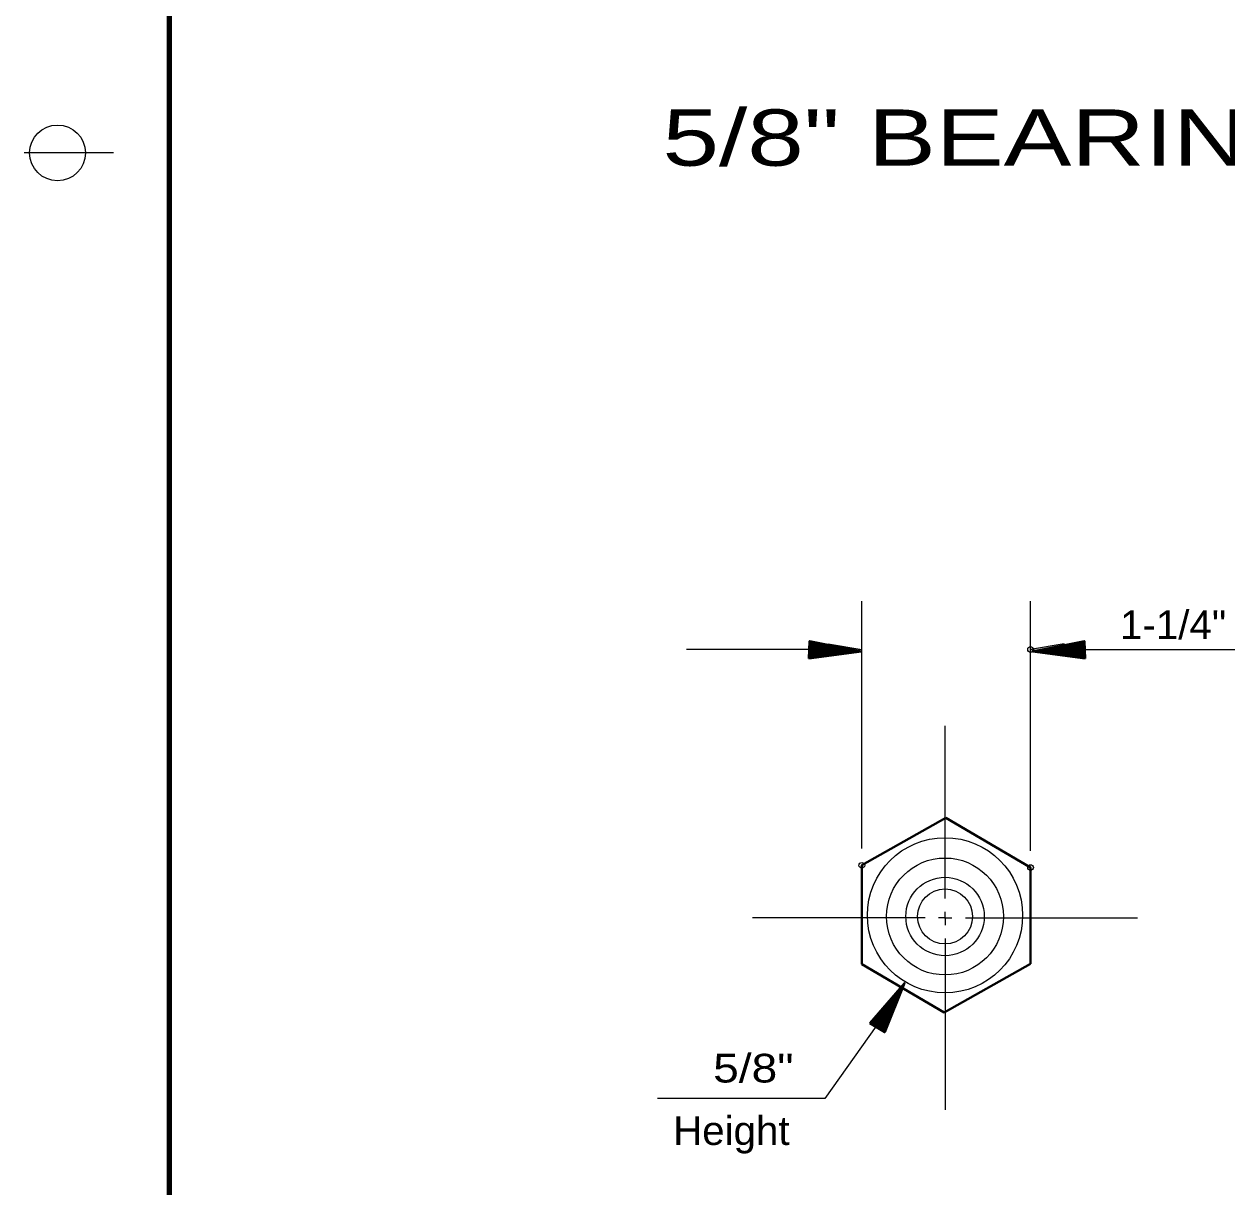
# Model space of a CAD drawing. Extents: x 895.6 to 930.4, y -2278.6 to -2254.7.
# Drawn here: x 896.79 to 902.18, y -2267.5 to -2262.29 of the extents above; entities that cross this region are included whole.
import ezdxf
from ezdxf.enums import TextEntityAlignment as Align

# ---------------------------------------------------------------- set-up
doc = ezdxf.new("R2010")
doc.units = 0
doc.header["$LTSCALE"] = 0.051
doc.header["$PDMODE"] = 32
doc.header["$PDSIZE"] = 0.0255
for name, color, linetype, lineweight in [('1', 7, 'Continuous', 70), ('3', 7, 'Continuous', 40), ('5', 7, 'Continuous', 25), ('6', 7, 'Continuous', 13)]:
    doc.layers.add(name, color=color, linetype=linetype, lineweight=lineweight)

msp = doc.modelspace()

# ---------------------------------------------------------------- hatches: boundary and pattern name
at = {"layer": '1'}
for points in [[(900.39442, -2265.11317), (900.39442, -2265.063), (900.545, -2265.08808), (900.545, -2265.08808)], [(901.45133, -2265.11317), (901.45133, -2265.063), (901.30075, -2265.08808), (901.30075, -2265.08808)]]:
    msp.add_hatch(color=256, dxfattribs=at).paths.add_polyline_path(points)
at = {"layer": '3'}
for points in [[(900.308, -2265.12892), (900.31067, -2265.05092), (900.54333, -2265.09783), (900.54333, -2265.09783)], [(900.30925, -2265.125), (900.31158, -2265.05483), (900.52092, -2265.097), (900.52092, -2265.097)], [(901.545, -2265.12892), (901.54233, -2265.05092), (901.30967, -2265.09783), (901.30967, -2265.09783)], [(901.54375, -2265.125), (901.54142, -2265.05483), (901.33208, -2265.097), (901.33208, -2265.097)], [(900.31025, -2265.1215), (900.31242, -2265.05842), (900.50083, -2265.09642), (900.50083, -2265.09642)], [(900.31125, -2265.11842), (900.31317, -2265.06167), (900.48275, -2265.09583), (900.48275, -2265.09583)], [(900.312, -2265.11575), (900.31383, -2265.06458), (900.4665, -2265.09533), (900.4665, -2265.09533)], [(900.313, -2265.11308), (900.3145, -2265.06708), (900.45183, -2265.09483), (900.45183, -2265.09483)], [(900.31358, -2265.11075), (900.31492, -2265.06933), (900.43867, -2265.09433), (900.43867, -2265.09433)], [(900.31433, -2265.10883), (900.31542, -2265.0715), (900.42667, -2265.094), (900.42667, -2265.094)], [(900.31467, -2265.107), (900.316, -2265.07333), (900.41608, -2265.0935), (900.41608, -2265.0935)], [(900.31533, -2265.10525), (900.31642, -2265.07492), (900.40642, -2265.09325), (900.40642, -2265.09325)], [(900.31583, -2265.10375), (900.31675, -2265.07658), (900.39775, -2265.09292), (900.39775, -2265.09292)], [(900.31617, -2265.10233), (900.31708, -2265.078), (900.39, -2265.09258), (900.39, -2265.09258)], [(900.31667, -2265.10125), (900.31733, -2265.07917), (900.38283, -2265.09242), (900.38283, -2265.09242)], [(900.31708, -2265.10008), (900.31758, -2265.08025), (900.37675, -2265.09225), (900.37675, -2265.09225)], [(900.31733, -2265.09917), (900.31792, -2265.08125), (900.371, -2265.09208), (900.371, -2265.09208)], [(900.31758, -2265.09825), (900.318, -2265.08208), (900.36592, -2265.09175), (900.36592, -2265.09175)], [(900.31783, -2265.09742), (900.31833, -2265.08283), (900.36133, -2265.09158), (900.36133, -2265.09158)], [(900.318, -2265.09667), (900.31842, -2265.08367), (900.35725, -2265.0915), (900.35725, -2265.0915)], [(900.31833, -2265.09625), (900.31858, -2265.08442), (900.35358, -2265.0915), (900.35358, -2265.0915)], [(900.3185, -2265.09567), (900.31883, -2265.08508), (900.35033, -2265.09142), (900.35033, -2265.09142)], [(900.31875, -2265.09533), (900.31908, -2265.08575), (900.34733, -2265.09158), (900.34733, -2265.09158)], [(900.31875, -2265.09475), (900.31908, -2265.08625), (900.34458, -2265.09142), (900.34458, -2265.09142)], [(900.31892, -2265.09425), (900.31925, -2265.08667), (900.34217, -2265.09117), (900.34217, -2265.09117)], [(900.31908, -2265.094), (900.31933, -2265.08717), (900.34, -2265.09125), (900.34, -2265.09125)], [(901.54275, -2265.1215), (901.54058, -2265.05842), (901.35217, -2265.09642), (901.35217, -2265.09642)], [(901.54175, -2265.11842), (901.53983, -2265.06167), (901.37025, -2265.09583), (901.37025, -2265.09583)], [(901.541, -2265.11575), (901.53917, -2265.06458), (901.3865, -2265.09533), (901.3865, -2265.09533)], [(901.54, -2265.11308), (901.5385, -2265.06708), (901.40117, -2265.09483), (901.40117, -2265.09483)], [(901.53942, -2265.11075), (901.53808, -2265.06933), (901.41433, -2265.09433), (901.41433, -2265.09433)], [(901.53867, -2265.10883), (901.53758, -2265.0715), (901.42633, -2265.094), (901.42633, -2265.094)], [(901.53833, -2265.107), (901.537, -2265.07333), (901.43692, -2265.0935), (901.43692, -2265.0935)], [(901.53767, -2265.10525), (901.53658, -2265.07492), (901.44658, -2265.09325), (901.44658, -2265.09325)], [(901.53717, -2265.10375), (901.53625, -2265.07658), (901.45525, -2265.09292), (901.45525, -2265.09292)], [(901.53683, -2265.10233), (901.53592, -2265.078), (901.463, -2265.09258), (901.463, -2265.09258)], [(901.53633, -2265.10125), (901.53567, -2265.07917), (901.47017, -2265.09242), (901.47017, -2265.09242)], [(901.53592, -2265.10008), (901.53542, -2265.08025), (901.47625, -2265.09225), (901.47625, -2265.09225)], [(901.53567, -2265.09917), (901.53508, -2265.08125), (901.482, -2265.09208), (901.482, -2265.09208)], [(901.53542, -2265.09825), (901.535, -2265.08208), (901.48708, -2265.09175), (901.48708, -2265.09175)], [(901.53517, -2265.09742), (901.53467, -2265.08283), (901.49167, -2265.09158), (901.49167, -2265.09158)], [(901.535, -2265.09667), (901.53458, -2265.08367), (901.49575, -2265.0915), (901.49575, -2265.0915)], [(901.53467, -2265.09625), (901.53442, -2265.08442), (901.49942, -2265.0915), (901.49942, -2265.0915)], [(901.5345, -2265.09567), (901.53417, -2265.08508), (901.50267, -2265.09142), (901.50267, -2265.09142)], [(901.53425, -2265.09533), (901.53392, -2265.08575), (901.50567, -2265.09158), (901.50567, -2265.09158)], [(901.53425, -2265.09475), (901.53392, -2265.08625), (901.50842, -2265.09142), (901.50842, -2265.09142)], [(901.53408, -2265.09425), (901.53375, -2265.08667), (901.51083, -2265.09117), (901.51083, -2265.09117)], [(901.53392, -2265.094), (901.53367, -2265.08717), (901.513, -2265.09125), (901.513, -2265.09125)], [(900.58158, -2266.76292), (900.64792, -2266.80358), (900.73608, -2266.583), (900.73608, -2266.583)], [(900.58533, -2266.76408), (900.64517, -2266.80025), (900.72442, -2266.60225), (900.72442, -2266.60225)], [(900.62183, -2266.715), (900.66292, -2266.744), (900.72958, -2266.60683), (900.72958, -2266.60683)], [(900.58883, -2266.765), (900.64267, -2266.79783), (900.714, -2266.61925), (900.714, -2266.61925)], [(900.59158, -2266.766), (900.64033, -2266.79542), (900.70475, -2266.63467), (900.70475, -2266.63467)], [(900.59442, -2266.76683), (900.63833, -2266.79325), (900.69608, -2266.64875), (900.69608, -2266.64875)], [(900.59692, -2266.76717), (900.63658, -2266.79117), (900.6885, -2266.66133), (900.6885, -2266.66133)], [(900.59933, -2266.76808), (900.635, -2266.78967), (900.68167, -2266.67225), (900.68167, -2266.67225)], [(900.60142, -2266.7685), (900.63325, -2266.78808), (900.6755, -2266.68292), (900.6755, -2266.68292)], [(900.60325, -2266.76925), (900.632, -2266.78675), (900.67, -2266.692), (900.67, -2266.692)], [(900.60508, -2266.76975), (900.63117, -2266.78533), (900.66508, -2266.7), (900.66508, -2266.7)], [(900.60658, -2266.77), (900.62992, -2266.78425), (900.66058, -2266.70733), (900.66058, -2266.70733)], [(900.60783, -2266.7705), (900.62883, -2266.78325), (900.6565, -2266.7145), (900.6565, -2266.7145)], [(900.60908, -2266.7705), (900.62783, -2266.78217), (900.65283, -2266.72008), (900.65283, -2266.72008)], [(900.61017, -2266.77117), (900.627, -2266.78142), (900.64975, -2266.72542), (900.64975, -2266.72542)], [(900.61108, -2266.77125), (900.6265, -2266.78083), (900.64667, -2266.73042), (900.64667, -2266.73042)], [(900.61192, -2266.77158), (900.62617, -2266.78), (900.64408, -2266.73483), (900.64408, -2266.73483)], [(900.61267, -2266.772), (900.62542, -2266.77933), (900.64183, -2266.73867), (900.64183, -2266.73867)], [(900.6135, -2266.772), (900.62467, -2266.77908), (900.63975, -2266.74225), (900.63975, -2266.74225)], [(900.61408, -2266.77208), (900.62433, -2266.7785), (900.63733, -2266.745), (900.63733, -2266.745)], [(900.61467, -2266.77242), (900.62392, -2266.77775), (900.636, -2266.74817), (900.636, -2266.74817)], [(900.615, -2266.77233), (900.62342, -2266.77742), (900.63408, -2266.7505), (900.63408, -2266.7505)], [(900.6155, -2266.77242), (900.62292, -2266.77708), (900.63267, -2266.75283), (900.63267, -2266.75283)], [(900.61608, -2266.7725), (900.62275, -2266.77667), (900.6315, -2266.755), (900.6315, -2266.755)], [(900.61633, -2266.77258), (900.62258, -2266.77608), (900.63033, -2266.75683), (900.63033, -2266.75683)]]:
    msp.add_hatch(color=256, dxfattribs=at).paths.add_polyline_path(points)

# ---------------------------------------------------------------- linework, layer by layer
at = {"layer": '1', "lineweight": 25}
for p, q in [((900.545, -2265.98017), (900.545, -2264.87125)), ((901.30075, -2265.99017), (901.30075, -2264.87125)), ((900.39442, -2265.08808), (899.75942, -2265.08808)), ((901.45133, -2265.08808), (901.602, -2265.08808)), ((901.602, -2265.08808), (902.63583, -2265.08808))]:
    msp.add_line(p, q, dxfattribs=at)
at = {"layer": '1', "lineweight": 40}
for p, q in [((900.92175, -2265.84317), (900.545, -2266.0555)), ((901.30075, -2266.0655), (900.92175, -2265.84317)), ((900.545, -2266.49858), (900.545, -2266.0555)), ((901.30075, -2266.49717), (901.30075, -2266.0655)), ((900.914, -2266.715), (900.545, -2266.49858)), ((901.30075, -2266.49717), (900.914, -2266.715))]:
    msp.add_line(p, q, dxfattribs=at)
at = {"layer": '1', "lineweight": 25}
for points in [[(900.39442, -2265.11317), (900.39442, -2265.063), (900.545, -2265.08808), (900.545, -2265.08808)], [(901.45133, -2265.11317), (901.45133, -2265.063), (901.30075, -2265.08808), (901.30075, -2265.08808)]]:
    msp.add_lwpolyline(points, close=True, dxfattribs=at)
for centre, radius in [((900.91774, -2266.27957), 0.34769), ((900.91774, -2266.28486), 0.26203), ((900.91774, -2266.28486), 0.12326)]:
    msp.add_circle(centre, radius, dxfattribs=at)
at = {"layer": '3', "lineweight": 158}
for q in [(897.44183, -2264.55975), (897.44183, -2277.16333)]:
    msp.add_line((897.44183, -2256.16333), q, dxfattribs=at)
at = {"layer": '3', "lineweight": 13}
for p, q in [((897.19183, -2262.86333), (896.79183, -2262.86333)), ((900.91783, -2266.29117), (900.88858, -2266.29117)), ((900.91783, -2266.29117), (900.91783, -2266.32417)), ((900.91783, -2266.29117), (900.94883, -2266.29117))]:
    msp.add_line(p, q, dxfattribs=at)
at = {"layer": '3', "lineweight": 25}
for p, q in [((900.91783, -2266.2035), (900.91783, -2265.43075)), ((900.82842, -2266.29117), (900.05567, -2266.29117)), ((900.91783, -2266.29392), (900.91783, -2266.264)), ((901.009, -2266.29117), (901.77992, -2266.29117)), ((900.91783, -2266.38417), (900.91783, -2267.1515))]:
    msp.add_line(p, q, dxfattribs=at)
at = {"layer": '3'}
for points in [[(900.308, -2265.12892), (900.31067, -2265.05092), (900.54333, -2265.09783), (900.54333, -2265.09783)], [(900.30925, -2265.125), (900.31158, -2265.05483), (900.52092, -2265.097), (900.52092, -2265.097)], [(901.545, -2265.12892), (901.54233, -2265.05092), (901.30967, -2265.09783), (901.30967, -2265.09783)], [(901.54375, -2265.125), (901.54142, -2265.05483), (901.33208, -2265.097), (901.33208, -2265.097)], [(900.31025, -2265.1215), (900.31242, -2265.05842), (900.50083, -2265.09642), (900.50083, -2265.09642)], [(900.31125, -2265.11842), (900.31317, -2265.06167), (900.48275, -2265.09583), (900.48275, -2265.09583)], [(900.312, -2265.11575), (900.31383, -2265.06458), (900.4665, -2265.09533), (900.4665, -2265.09533)], [(900.313, -2265.11308), (900.3145, -2265.06708), (900.45183, -2265.09483), (900.45183, -2265.09483)], [(900.31358, -2265.11075), (900.31492, -2265.06933), (900.43867, -2265.09433), (900.43867, -2265.09433)], [(900.31433, -2265.10883), (900.31542, -2265.0715), (900.42667, -2265.094), (900.42667, -2265.094)], [(900.31467, -2265.107), (900.316, -2265.07333), (900.41608, -2265.0935), (900.41608, -2265.0935)], [(900.31533, -2265.10525), (900.31642, -2265.07492), (900.40642, -2265.09325), (900.40642, -2265.09325)], [(900.31583, -2265.10375), (900.31675, -2265.07658), (900.39775, -2265.09292), (900.39775, -2265.09292)], [(900.31617, -2265.10233), (900.31708, -2265.078), (900.39, -2265.09258), (900.39, -2265.09258)], [(900.31667, -2265.10125), (900.31733, -2265.07917), (900.38283, -2265.09242), (900.38283, -2265.09242)], [(900.31708, -2265.10008), (900.31758, -2265.08025), (900.37675, -2265.09225), (900.37675, -2265.09225)], [(900.31733, -2265.09917), (900.31792, -2265.08125), (900.371, -2265.09208), (900.371, -2265.09208)], [(900.31758, -2265.09825), (900.318, -2265.08208), (900.36592, -2265.09175), (900.36592, -2265.09175)], [(900.31783, -2265.09742), (900.31833, -2265.08283), (900.36133, -2265.09158), (900.36133, -2265.09158)], [(900.318, -2265.09667), (900.31842, -2265.08367), (900.35725, -2265.0915), (900.35725, -2265.0915)], [(900.31833, -2265.09625), (900.31858, -2265.08442), (900.35358, -2265.0915), (900.35358, -2265.0915)], [(900.3185, -2265.09567), (900.31883, -2265.08508), (900.35033, -2265.09142), (900.35033, -2265.09142)], [(900.31875, -2265.09533), (900.31908, -2265.08575), (900.34733, -2265.09158), (900.34733, -2265.09158)], [(900.31875, -2265.09475), (900.31908, -2265.08625), (900.34458, -2265.09142), (900.34458, -2265.09142)], [(900.31892, -2265.09425), (900.31925, -2265.08667), (900.34217, -2265.09117), (900.34217, -2265.09117)], [(900.31908, -2265.094), (900.31933, -2265.08717), (900.34, -2265.09125), (900.34, -2265.09125)], [(901.54275, -2265.1215), (901.54058, -2265.05842), (901.35217, -2265.09642), (901.35217, -2265.09642)], [(901.54175, -2265.11842), (901.53983, -2265.06167), (901.37025, -2265.09583), (901.37025, -2265.09583)], [(901.541, -2265.11575), (901.53917, -2265.06458), (901.3865, -2265.09533), (901.3865, -2265.09533)], [(901.54, -2265.11308), (901.5385, -2265.06708), (901.40117, -2265.09483), (901.40117, -2265.09483)], [(901.53942, -2265.11075), (901.53808, -2265.06933), (901.41433, -2265.09433), (901.41433, -2265.09433)], [(901.53867, -2265.10883), (901.53758, -2265.0715), (901.42633, -2265.094), (901.42633, -2265.094)], [(901.53833, -2265.107), (901.537, -2265.07333), (901.43692, -2265.0935), (901.43692, -2265.0935)], [(901.53767, -2265.10525), (901.53658, -2265.07492), (901.44658, -2265.09325), (901.44658, -2265.09325)], [(901.53717, -2265.10375), (901.53625, -2265.07658), (901.45525, -2265.09292), (901.45525, -2265.09292)], [(901.53683, -2265.10233), (901.53592, -2265.078), (901.463, -2265.09258), (901.463, -2265.09258)], [(901.53633, -2265.10125), (901.53567, -2265.07917), (901.47017, -2265.09242), (901.47017, -2265.09242)], [(901.53592, -2265.10008), (901.53542, -2265.08025), (901.47625, -2265.09225), (901.47625, -2265.09225)], [(901.53567, -2265.09917), (901.53508, -2265.08125), (901.482, -2265.09208), (901.482, -2265.09208)], [(901.53542, -2265.09825), (901.535, -2265.08208), (901.48708, -2265.09175), (901.48708, -2265.09175)], [(901.53517, -2265.09742), (901.53467, -2265.08283), (901.49167, -2265.09158), (901.49167, -2265.09158)], [(901.535, -2265.09667), (901.53458, -2265.08367), (901.49575, -2265.0915), (901.49575, -2265.0915)], [(901.53467, -2265.09625), (901.53442, -2265.08442), (901.49942, -2265.0915), (901.49942, -2265.0915)], [(901.5345, -2265.09567), (901.53417, -2265.08508), (901.50267, -2265.09142), (901.50267, -2265.09142)], [(901.53425, -2265.09533), (901.53392, -2265.08575), (901.50567, -2265.09158), (901.50567, -2265.09158)], [(901.53425, -2265.09475), (901.53392, -2265.08625), (901.50842, -2265.09142), (901.50842, -2265.09142)], [(901.53408, -2265.09425), (901.53375, -2265.08667), (901.51083, -2265.09117), (901.51083, -2265.09117)], [(901.53392, -2265.094), (901.53367, -2265.08717), (901.513, -2265.09125), (901.513, -2265.09125)], [(900.58158, -2266.76292), (900.64792, -2266.80358), (900.73608, -2266.583), (900.73608, -2266.583)], [(900.58533, -2266.76408), (900.64517, -2266.80025), (900.72442, -2266.60225), (900.72442, -2266.60225)], [(900.58883, -2266.765), (900.64267, -2266.79783), (900.714, -2266.61925), (900.714, -2266.61925)], [(900.59158, -2266.766), (900.64033, -2266.79542), (900.70475, -2266.63467), (900.70475, -2266.63467)], [(900.59442, -2266.76683), (900.63833, -2266.79325), (900.69608, -2266.64875), (900.69608, -2266.64875)], [(900.59692, -2266.76717), (900.63658, -2266.79117), (900.6885, -2266.66133), (900.6885, -2266.66133)], [(900.59933, -2266.76808), (900.635, -2266.78967), (900.68167, -2266.67225), (900.68167, -2266.67225)], [(900.60142, -2266.7685), (900.63325, -2266.78808), (900.6755, -2266.68292), (900.6755, -2266.68292)], [(900.60325, -2266.76925), (900.632, -2266.78675), (900.67, -2266.692), (900.67, -2266.692)], [(900.60508, -2266.76975), (900.63117, -2266.78533), (900.66508, -2266.7), (900.66508, -2266.7)], [(900.60658, -2266.77), (900.62992, -2266.78425), (900.66058, -2266.70733), (900.66058, -2266.70733)], [(900.60783, -2266.7705), (900.62883, -2266.78325), (900.6565, -2266.7145), (900.6565, -2266.7145)], [(900.60908, -2266.7705), (900.62783, -2266.78217), (900.65283, -2266.72008), (900.65283, -2266.72008)], [(900.61017, -2266.77117), (900.627, -2266.78142), (900.64975, -2266.72542), (900.64975, -2266.72542)], [(900.61108, -2266.77125), (900.6265, -2266.78083), (900.64667, -2266.73042), (900.64667, -2266.73042)], [(900.61192, -2266.77158), (900.62617, -2266.78), (900.64408, -2266.73483), (900.64408, -2266.73483)], [(900.61267, -2266.772), (900.62542, -2266.77933), (900.64183, -2266.73867), (900.64183, -2266.73867)], [(900.6135, -2266.772), (900.62467, -2266.77908), (900.63975, -2266.74225), (900.63975, -2266.74225)], [(900.61408, -2266.77208), (900.62433, -2266.7785), (900.63733, -2266.745), (900.63733, -2266.745)], [(900.61467, -2266.77242), (900.62392, -2266.77775), (900.636, -2266.74817), (900.636, -2266.74817)], [(900.615, -2266.77233), (900.62342, -2266.77742), (900.63408, -2266.7505), (900.63408, -2266.7505)], [(900.6155, -2266.77242), (900.62292, -2266.77708), (900.63267, -2266.75283), (900.63267, -2266.75283)], [(900.61608, -2266.7725), (900.62275, -2266.77667), (900.6315, -2266.755), (900.6315, -2266.755)], [(900.61633, -2266.77258), (900.62258, -2266.77608), (900.63033, -2266.75683), (900.63033, -2266.75683)]]:
    msp.add_lwpolyline(points, close=True, dxfattribs=at)
at = {"layer": '3', "lineweight": 13}
msp.add_lwpolyline([(900.62183, -2266.715), (900.66292, -2266.744), (900.72958, -2266.60683), (900.72958, -2266.60683)], close=True, dxfattribs=at)
at = {"layer": '3', "lineweight": 25}
msp.add_lwpolyline([(900.64242, -2266.72942), (900.37875, -2267.10067), (899.63008, -2267.10067)], dxfattribs=at)
at = {"layer": '3', "lineweight": 13}
msp.add_circle((896.94183, -2262.86333), 0.125, dxfattribs=at)
at = {"layer": '5'}
msp.add_circle((900.91774, -2266.28486), 0.1757, dxfattribs=at)
at = {"layer": '6'}
for p in [(901.30075, -2265.08808), (900.545, -2266.0555), (901.30075, -2266.0655)]:
    msp.add_point(p, dxfattribs=at)

# ---------------------------------------------------------------- texts
at = {"layer": '1', "width": 1.35}
msp.add_text('5/8" BEARING PLATE DETAIL', height=0.2522, dxfattribs=at).set_placement((902.78183, -2262.92067), align=Align.CENTER)
at = {"layer": '1', "width": 1.05}
msp.add_text('1-1/4"', height=0.1286, dxfattribs=at).set_placement((901.70175, -2265.042))
at = {"layer": '3'}
for s, width, p in [('5/8"', 1.2, (899.87908, -2267.02883)), ('Height', 1.05, (899.69958, -2267.30875))]:
    msp.add_text(s, height=0.1286, dxfattribs=dict(at, width=width)).set_placement(p)

doc.saveas('drawing.dxf')
